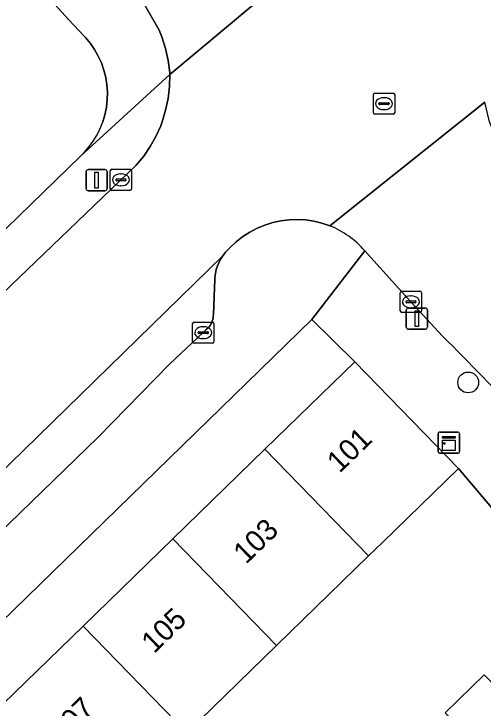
# Model space of a CAD drawing. Extents: x 159217 to 160349, y 381246 to 382172.
# Drawn here: x 159595.21 to 159617.29, y 381472.41 to 381505.08 of the extents above; entities that cross this region are included whole.
import ezdxf

# ---------------------------------------------------------------- set-up
doc = ezdxf.new("R2010")
doc.units = 0
for name, color, linetype in [('IMGEO_Boom', 7, 'Continuous'), ('IMGEO_Erf', 7, 'Continuous'), ('IMGEO_Haag', 7, 'Continuous'), ('IMGEO_Kast', 7, 'Continuous'), ('IMGEO_Kolk', 7, 'Continuous'), ('IMGEO_Lichtmast', 7, 'Continuous'), ('IMGEO_Muur', 7, 'Continuous'), ('IMGEO_Pand', 7, 'Continuous'), ('IMGEO_Pand_nummerreeks', 7, 'Continuous'), ('IMGEO_Parkeervlak_gesloten', 7, 'Continuous'), ('IMGEO_Rijbaan_lokaal_gesloten', 7, 'Continuous'), ('IMGEO_Rijbaan_lokaal_open', 7, 'Continuous'), ('IMGEO_Rioolput', 7, 'Continuous'), ('IMGEO_Voetpad_open', 7, 'Continuous')]:
    doc.layers.add(name, color=color, linetype=linetype)

msp = doc.modelspace()

# ---------------------------------------------------------------- linework, layer by layer
at = {"layer": 'IMGEO_Boom'}
msp.add_circle((159616.591, 381487.737), 0.489, dxfattribs=at)
at = {"layer": 'IMGEO_Erf'}
for points in [[(159599.397, 381500), (159599.498, 381500.339), (159599.569, 381500.686), (159599.609, 381501.038), (159599.616, 381501.392), (159599.593, 381501.746), (159599.537, 381502.095), (159599.451, 381502.439), (159599.334, 381502.773), (159599.188, 381503.096), (159599.014, 381503.404), (159598.813, 381503.695), (159598.586, 381503.968), (159598.538, 381504.02), (159597.784, 381504.824), (159590.258, 381513.08), (159579.357, 381524.607), (159568.355, 381536.063), (159563.311, 381541.305), (159563.005, 381541.713), (159558.611, 381546.23)], [(159539.065, 381507.732), (159532.866, 381501.64), (159533.78, 381500.754), (159533.92, 381500.619), (159533.288, 381500), (159529.255, 381496.05), (159533.836, 381491.161), (159535.126, 381489.785), (159537.084, 381488.236), (159540.616, 381491.711), (159541.068, 381492.156), (159539.687, 381493.589), (159546.206, 381500), (159559.807, 381513.376), (159572.893, 381500), (159586.111, 381486.49), (159598.343, 381498.393)], [(159594.136, 381472.057), (159598.471, 381476.273), (159602.688, 381480.373), (159607.022, 381484.589), (159611.256, 381488.706), (159609.226, 381490.692), (159573.857, 381456.231)], [(159623.522, 381474.971), (159616.137, 381483.686), (159612.553, 381480.201), (159611.904, 381479.569), (159607.569, 381475.354), (159603.352, 381471.254)], [(159615.499, 381472.19), (159617.339, 381473.98)]]:
    msp.add_lwpolyline(points, dxfattribs=at)
msp.add_arc((159595.668, 381501.297), 3.949, 312.6552, 340.8246, dxfattribs=at)
at = {"layer": 'IMGEO_Haag'}
for points in [[(159599.397, 381500), (159599.498, 381500.339), (159599.569, 381500.686), (159599.609, 381501.038), (159599.616, 381501.392), (159599.593, 381501.746), (159599.537, 381502.095), (159599.451, 381502.439), (159599.334, 381502.773), (159599.188, 381503.096), (159599.014, 381503.404), (159598.813, 381503.695), (159598.586, 381503.968), (159598.538, 381504.02), (159597.784, 381504.824), (159590.258, 381513.08), (159579.357, 381524.607), (159568.355, 381536.063), (159563.311, 381541.305), (159563.005, 381541.713), (159558.611, 381546.23)], [(159539.065, 381507.732), (159532.866, 381501.64), (159533.78, 381500.754), (159533.92, 381500.619), (159533.288, 381500), (159529.255, 381496.05), (159533.836, 381491.161), (159535.126, 381489.785), (159537.084, 381488.236), (159540.616, 381491.711), (159541.068, 381492.156), (159539.687, 381493.589), (159546.206, 381500), (159559.807, 381513.376), (159572.893, 381500), (159586.111, 381486.49), (159598.343, 381498.393)]]:
    msp.add_lwpolyline(points, dxfattribs=at)
msp.add_arc((159595.668, 381501.297), 3.949, 312.6552, 340.8246, dxfattribs=at)
at = {"layer": 'IMGEO_Kast'}
for p, q in [((159615.178, 381484.477), (159615.178, 381485.318)), ((159615.178, 381485.318), (159615.178, 381484.477)), ((159615.253, 381485.402), (159616.094, 381485.402)), ((159616.094, 381485.402), (159615.253, 381485.402)), ((159616.178, 381485.327), (159616.178, 381484.486)), ((159616.178, 381484.486), (159616.178, 381485.327)), ((159616.103, 381484.402), (159615.262, 381484.402)), ((159615.262, 381484.402), (159616.103, 381484.402))]:
    msp.add_line(p, q, dxfattribs=at)
for points in [[(159615.373, 381485.192), (159615.973, 381485.192), (159615.973, 381485.107), (159615.373, 381485.107), (159615.373, 381485.192)], [(159615.373, 381485.017), (159615.973, 381485.017), (159615.973, 381484.528), (159615.373, 381484.528), (159615.373, 381485.017)]]:
    msp.add_lwpolyline(points, dxfattribs=at)
msp.add_circle((159615.457, 381484.866), 0.0377, dxfattribs=at)
for centre, start, end in [((159615.256, 381485.324), 92.4484, 184.2845), ((159615.256, 381485.324), 92.4484, 184.2845), ((159616.1, 381485.324), 2.4484, 94.2845), ((159616.1, 381485.324), 2.4484, 94.2845), ((159615.256, 381484.48), 182.4484, 274.2845), ((159615.256, 381484.48), 182.4484, 274.2845), ((159616.1, 381484.48), 272.4484, 4.2845), ((159616.1, 381484.48), 272.4484, 4.2845)]:
    msp.add_arc(centre, 0.0779, start, end, dxfattribs=at)
at = {"layer": 'IMGEO_Kolk'}
for p, q in [((159599.75, 381496.846), (159599.75, 381497.698)), ((159599.825, 381497.772), (159600.677, 381497.772)), ((159600.751, 381497.698), (159600.751, 381496.846)), ((159600.052, 381497.315), (159600.45, 381497.315)), ((159600.238, 381497.552), (159600.263, 381497.552)), ((159600.009, 381497.266), (159600.009, 381497.278)), ((159600.447, 381497.229), (159600.049, 381497.229)), ((159600.261, 381496.992), (159600.236, 381496.992)), ((159600.493, 381497.278), (159600.493, 381497.266)), ((159600.677, 381496.772), (159599.825, 381496.772)), ((159613.394, 381491.105), (159613.394, 381491.957)), ((159613.469, 381492.031), (159614.321, 381492.031)), ((159613.882, 381491.811), (159613.907, 381491.811)), ((159614.395, 381491.957), (159614.395, 381491.105)), ((159613.653, 381491.525), (159613.653, 381491.537)), ((159614.091, 381491.488), (159613.693, 381491.488)), ((159613.696, 381491.574), (159614.094, 381491.574)), ((159614.137, 381491.537), (159614.137, 381491.525)), ((159613.905, 381491.251), (159613.88, 381491.251)), ((159614.321, 381491.031), (159613.469, 381491.031)), ((159603.623, 381489.653), (159603.623, 381490.505)), ((159603.698, 381490.579), (159604.55, 381490.579)), ((159604.624, 381490.505), (159604.624, 381489.653)), ((159603.925, 381490.122), (159604.323, 381490.122)), ((159604.111, 381490.359), (159604.136, 381490.359)), ((159603.882, 381490.073), (159603.882, 381490.085)), ((159604.32, 381490.036), (159603.922, 381490.036)), ((159604.134, 381489.799), (159604.109, 381489.799)), ((159604.366, 381490.085), (159604.366, 381490.073)), ((159604.55, 381489.579), (159603.698, 381489.579))]:
    msp.add_line(p, q, dxfattribs=at)
for points in [[(159599.75, 381496.846), (159599.75, 381497.698)], [(159599.825, 381497.772), (159600.677, 381497.772)], [(159600.751, 381497.698), (159600.751, 381496.846)], [(159600.677, 381496.772), (159599.825, 381496.772)], [(159613.394, 381491.105), (159613.394, 381491.957)], [(159613.469, 381492.031), (159614.321, 381492.031)], [(159614.395, 381491.957), (159614.395, 381491.105)], [(159614.321, 381491.031), (159613.469, 381491.031)], [(159603.623, 381489.653), (159603.623, 381490.505)], [(159603.698, 381490.579), (159604.55, 381490.579)], [(159604.624, 381490.505), (159604.624, 381489.653)], [(159604.55, 381489.579), (159603.698, 381489.579)]]:
    msp.add_lwpolyline(points, dxfattribs=at)
for centre, radius, start, end in [((159599.827, 381497.696), 0.0765, 91.552, 178.448), ((159599.827, 381497.696), 0.0765, 91.552, 178.448), ((159600.675, 381497.696), 0.0765, 1.552, 88.448), ((159600.675, 381497.696), 0.0765, 1.552, 88.448), ((159600.049, 381497.275), 0.0403, 85.8775, 175.7526), ((159600.454, 381497.277), 0.0386, 1.7309, 96.639), ((159600.046, 381497.265), 0.0366, 178.938, 274.7102), ((159600.45, 381497.272), 0.043, 264.8664, 352.4533), ((159599.827, 381496.848), 0.0765, 181.552, 268.448), ((159599.827, 381496.848), 0.0765, 181.552, 268.448), ((159600.675, 381496.848), 0.0765, 271.552, 358.448), ((159600.675, 381496.848), 0.0765, 271.552, 358.448), ((159613.471, 381491.955), 0.0765, 91.552, 178.448), ((159613.471, 381491.955), 0.0765, 91.552, 178.448), ((159614.319, 381491.955), 0.0765, 1.552, 88.448), ((159614.319, 381491.955), 0.0765, 1.552, 88.448), ((159613.693, 381491.534), 0.0403, 85.8775, 175.7526), ((159613.69, 381491.524), 0.0366, 178.938, 274.7102), ((159614.094, 381491.531), 0.043, 264.8664, 352.4533), ((159614.098, 381491.536), 0.0386, 1.7309, 96.639), ((159613.471, 381491.107), 0.0765, 181.552, 268.448), ((159613.471, 381491.107), 0.0765, 181.552, 268.448), ((159614.319, 381491.107), 0.0765, 271.552, 358.448), ((159614.319, 381491.107), 0.0765, 271.552, 358.448), ((159603.7, 381490.503), 0.0765, 91.552, 178.448), ((159603.7, 381490.503), 0.0765, 91.552, 178.448), ((159604.548, 381490.503), 0.0765, 1.552, 88.448), ((159604.548, 381490.503), 0.0765, 1.552, 88.448), ((159603.922, 381490.082), 0.0403, 85.8775, 175.7526), ((159604.327, 381490.084), 0.0386, 1.7309, 96.639), ((159603.919, 381490.072), 0.0366, 178.938, 274.7102), ((159604.323, 381490.079), 0.043, 264.8664, 352.4533), ((159603.7, 381489.655), 0.0765, 181.552, 268.448), ((159603.7, 381489.655), 0.0765, 181.552, 268.448), ((159604.548, 381489.655), 0.0765, 271.552, 358.448), ((159604.548, 381489.655), 0.0765, 271.552, 358.448)]:
    msp.add_arc(centre, radius, start, end, dxfattribs=at)
for centre, major_axis, ratio, start_param, end_param in [((159600.237, 381497.272), (-0.387, 0.002), 0.722429, 4.712389, 7.853982), ((159600.262, 381497.272), (-0.39, 0.002), 0.717154, 1.570796, 4.712389), ((159613.881, 381491.531), (-0.387, 0.002), 0.722429, 4.712389, 7.853982), ((159613.906, 381491.531), (-0.39, 0.002), 0.717154, 1.570796, 4.712389), ((159604.11, 381490.079), (-0.387, 0.002), 0.722429, 4.712389, 7.853982), ((159604.135, 381490.079), (-0.39, 0.002), 0.717154, 1.570796, 4.712389)]:
    msp.add_ellipse(centre, major_axis=major_axis, ratio=ratio, start_param=start_param, end_param=end_param, dxfattribs=at)
at = {"layer": 'IMGEO_Lichtmast'}
for p, q in [((159598.611, 381496.858), (159598.611, 381497.658)), ((159598.611, 381497.658), (159598.611, 381496.858)), ((159598.711, 381497.758), (159599.501, 381497.758)), ((159599.501, 381497.758), (159598.711, 381497.758)), ((159599.601, 381497.658), (159599.601, 381496.858)), ((159599.601, 381496.858), (159599.601, 381497.658)), ((159599.501, 381496.758), (159598.711, 381496.758)), ((159598.711, 381496.758), (159599.501, 381496.758)), ((159613.679, 381490.339), (159613.679, 381491.139)), ((159613.679, 381491.139), (159613.679, 381490.339)), ((159613.779, 381491.239), (159614.569, 381491.239)), ((159614.569, 381491.239), (159613.779, 381491.239)), ((159614.669, 381491.139), (159614.669, 381490.339)), ((159614.669, 381490.339), (159614.669, 381491.139)), ((159614.569, 381490.239), (159613.779, 381490.239)), ((159613.779, 381490.239), (159614.569, 381490.239))]:
    msp.add_line(p, q, dxfattribs=at)
for points in [[(159599.031, 381497.633), (159599.181, 381497.633), (159599.181, 381496.883), (159599.031, 381496.883), (159599.031, 381497.633)], [(159614.099, 381491.114), (159614.249, 381491.114), (159614.249, 381490.364), (159614.099, 381490.364), (159614.099, 381491.114)]]:
    msp.add_lwpolyline(points, dxfattribs=at)
for centre, start, end in [((159598.711, 381497.658), 90, 180), ((159598.711, 381497.658), 90, 180), ((159599.501, 381497.658), 0, 90), ((159599.501, 381497.658), 360, 90), ((159598.711, 381496.858), 180, 270), ((159598.711, 381496.858), 180, 270), ((159599.501, 381496.858), 270, 0), ((159599.501, 381496.858), 270, 0), ((159613.779, 381491.139), 90, 180), ((159613.779, 381491.139), 90, 180), ((159614.569, 381491.139), 0, 90), ((159614.569, 381491.139), 360, 90), ((159613.779, 381490.339), 180, 270), ((159613.779, 381490.339), 180, 270), ((159614.569, 381490.339), 270, 0), ((159614.569, 381490.339), 270, 0)]:
    msp.add_arc(centre, 0.1, start, end, dxfattribs=at)
at = {"layer": 'IMGEO_Muur'}
msp.add_lwpolyline([(159616.137, 381483.686), (159623.522, 381474.971)], dxfattribs=at)
at = {"layer": 'IMGEO_Pand'}
for points in [[(159611.904, 381479.569), (159612.553, 381480.201), (159616.137, 381483.686), (159611.256, 381488.706), (159607.022, 381484.589)], [(159611.904, 381479.569), (159607.022, 381484.589), (159602.688, 381480.373), (159607.569, 381475.354)], [(159602.688, 381480.373), (159598.471, 381476.273), (159603.352, 381471.254), (159607.569, 381475.354)], [(159599.017, 381467.038), (159603.352, 381471.254), (159598.471, 381476.273), (159594.136, 381472.057)], [(159617.339, 381473.98), (159615.499, 381472.19), (159618.009, 381469.609), (159619.849, 381471.399)]]:
    msp.add_lwpolyline(points, close=True, dxfattribs=at)
at = {"layer": 'IMGEO_Parkeervlak_gesloten'}
msp.add_lwpolyline([(159582.905, 381469.38), (159599.187, 381485.169), (159602.545, 381488.611), (159604.123, 381490.08), (159604.284, 381490.241), (159604.342, 381490.295), (159604.396, 381490.353), (159604.443, 381490.416), (159604.485, 381490.483), (159604.521, 381490.554), (159604.551, 381490.627), (159604.573, 381490.703), (159604.589, 381490.78), (159604.598, 381490.859), (159604.6, 381490.931), (159604.668, 381492.597), (159604.673, 381492.68), (159604.698, 381492.865), (159604.738, 381493.047), (159604.795, 381493.224), (159604.867, 381493.396), (159604.955, 381493.561), (159605.042, 381493.695), (159561.561, 381451.233)], dxfattribs=at)
at = {"layer": 'IMGEO_Rijbaan_lokaal_gesloten'}
for points in [[(159558.685, 381551.263), (159562.533, 381546.538), (159565.152, 381543.854), (159567.81, 381540.95), (159578.666, 381529.864), (159592.512, 381515.439), (159599.596, 381507.693), (159601.31, 381505.606), (159602.056, 381504.314), (159602.178, 381504.004), (159602.351, 381503.454), (159602.474, 381502.891), (159602.546, 381502.319), (159602.548, 381502.232), (159610.359, 381508.766), (159609.93, 381508.934), (159609.517, 381509.14), (159609.125, 381509.381), (159608.755, 381509.657), (159608.412, 381509.965)], [(159610.359, 381508.766), (159602.548, 381502.232), (159602.535, 381501.664), (159602.47, 381501.1), (159602.356, 381500.544), (159602.192, 381500), (159602.122, 381499.813), (159601.898, 381499.315), (159601.631, 381498.839), (159601.322, 381498.388), (159600.974, 381497.967), (159589.128, 381486.611), (159587.265, 381484.884)], [(159561.561, 381451.233), (159605.042, 381493.695), (159605.057, 381493.718), (159605.172, 381493.864), (159605.3, 381494), (159605.386, 381494.09), (159605.672, 381494.357), (159605.981, 381494.598), (159606.31, 381494.809), (159606.657, 381494.991), (159607.018, 381495.141), (159607.391, 381495.258), (159607.774, 381495.341), (159608.162, 381495.389), (159608.553, 381495.403), (159608.943, 381495.382), (159609.331, 381495.326), (159609.711, 381495.236), (159610.082, 381495.112), (159616.217, 381500), (159617.375, 381500.923)]]:
    msp.add_lwpolyline(points, dxfattribs=at)
at = {"layer": 'IMGEO_Rijbaan_lokaal_open'}
for points in [[(159641.019, 381472.846), (159632.882, 381482.53), (159627.569, 381488.79), (159622.028, 381494.6), (159619.537, 381497.357), (159618.573, 381498.425), (159618.392, 381498.626), (159618.148, 381498.941), (159617.933, 381499.277), (159617.75, 381499.631), (159617.598, 381500), (159617.375, 381500.923), (159616.217, 381500), (159610.082, 381495.112)], [(159611.723, 381493.938), (159613.896, 381491.532), (159615.382, 381489.917)]]:
    msp.add_lwpolyline(points, dxfattribs=at)
for centre, radius, start, end in [((159608.359, 381490.97), 4.486, 41.4231, 67.4157), ((159522.53, 381396.515), 131.702, 40.47009, 45.16941)]:
    msp.add_arc(centre, radius, start, end, dxfattribs=at)
at = {"layer": 'IMGEO_Rioolput'}
for p, q in [((159612.13, 381500.432), (159612.13, 381501.284)), ((159612.205, 381501.358), (159613.057, 381501.358)), ((159613.131, 381501.284), (159613.131, 381500.432)), ((159612.432, 381500.901), (159612.83, 381500.901)), ((159612.618, 381501.138), (159612.643, 381501.138)), ((159612.389, 381500.852), (159612.389, 381500.864)), ((159612.827, 381500.815), (159612.429, 381500.815)), ((159612.641, 381500.578), (159612.616, 381500.578)), ((159612.873, 381500.864), (159612.873, 381500.852)), ((159613.057, 381500.358), (159612.205, 381500.358))]:
    msp.add_line(p, q, dxfattribs=at)
for points in [[(159612.13, 381500.432), (159612.13, 381501.284)], [(159612.205, 381501.358), (159613.057, 381501.358)], [(159613.131, 381501.284), (159613.131, 381500.432)], [(159613.057, 381500.358), (159612.205, 381500.358)]]:
    msp.add_lwpolyline(points, dxfattribs=at)
for centre, radius, start, end in [((159612.207, 381501.282), 0.0765, 91.552, 178.448), ((159612.207, 381501.282), 0.0765, 91.552, 178.448), ((159613.055, 381501.282), 0.0765, 1.552, 88.448), ((159613.055, 381501.282), 0.0765, 1.552, 88.448), ((159612.429, 381500.861), 0.0403, 85.8775, 175.7526), ((159612.834, 381500.863), 0.0386, 1.7309, 96.639), ((159612.426, 381500.851), 0.0366, 178.938, 274.7102), ((159612.83, 381500.858), 0.043, 264.8664, 352.4533), ((159612.207, 381500.434), 0.0765, 181.552, 268.448), ((159612.207, 381500.434), 0.0765, 181.552, 268.448), ((159613.055, 381500.434), 0.0765, 271.552, 358.448), ((159613.055, 381500.434), 0.0765, 271.552, 358.448)]:
    msp.add_arc(centre, radius, start, end, dxfattribs=at)
for centre, major_axis, ratio, start_param, end_param in [((159612.617, 381500.858), (-0.387, 0.002), 0.722429, 4.712389, 7.853982), ((159612.642, 381500.858), (-0.39, 0.002), 0.717154, 1.570796, 4.712389)]:
    msp.add_ellipse(centre, major_axis=major_axis, ratio=ratio, start_param=start_param, end_param=end_param, dxfattribs=at)
at = {"layer": 'IMGEO_Voetpad_open'}
for points in [[(159558.611, 381546.23), (159563.005, 381541.713), (159563.311, 381541.305), (159568.355, 381536.063), (159579.357, 381524.607), (159590.258, 381513.08), (159597.784, 381504.824), (159598.538, 381504.02), (159598.586, 381503.968), (159598.813, 381503.695), (159599.014, 381503.404), (159599.188, 381503.096), (159599.334, 381502.773), (159599.451, 381502.439), (159599.537, 381502.095), (159599.593, 381501.746), (159599.616, 381501.392), (159599.609, 381501.038), (159599.569, 381500.686), (159599.498, 381500.339), (159599.397, 381500)], [(159598.343, 381498.393), (159602.548, 381502.232), (159602.546, 381502.319), (159602.474, 381502.891), (159602.351, 381503.454), (159602.178, 381504.004), (159602.056, 381504.314), (159601.31, 381505.606), (159599.596, 381507.693), (159592.512, 381515.439)], [(159600.974, 381497.967), (159601.322, 381498.388), (159601.631, 381498.839), (159601.898, 381499.315), (159602.122, 381499.813), (159602.192, 381500), (159602.356, 381500.544), (159602.47, 381501.1), (159602.535, 381501.664), (159602.548, 381502.232), (159598.343, 381498.393), (159586.111, 381486.49), (159584.818, 381485.232), (159571.706, 381472.473), (159568.157, 381468.986), (159562.025, 381462.991), (159559.843, 381460.857), (159544.065, 381445.432)], [(159587.265, 381484.884), (159589.128, 381486.611), (159600.974, 381497.967)], [(159610.082, 381495.112), (159609.711, 381495.236), (159609.331, 381495.326), (159608.943, 381495.382), (159608.553, 381495.403), (159608.162, 381495.389), (159607.774, 381495.341), (159607.391, 381495.258), (159607.018, 381495.141), (159606.657, 381494.991), (159606.31, 381494.809), (159605.981, 381494.598), (159605.672, 381494.357), (159605.386, 381494.09), (159605.3, 381494), (159605.172, 381493.864), (159605.057, 381493.718), (159605.042, 381493.695), (159604.955, 381493.561), (159604.867, 381493.396), (159604.795, 381493.224), (159604.738, 381493.047), (159604.698, 381492.865), (159604.673, 381492.68), (159604.668, 381492.597), (159604.6, 381490.931), (159604.598, 381490.859), (159604.589, 381490.78), (159604.573, 381490.703), (159604.551, 381490.627), (159604.521, 381490.554), (159604.485, 381490.483), (159604.443, 381490.416), (159604.396, 381490.353), (159604.342, 381490.295), (159604.284, 381490.241), (159604.123, 381490.08), (159602.545, 381488.611), (159599.187, 381485.169), (159582.905, 381469.38)], [(159539.277, 381422.576), (159544.261, 381427.431), (159554.351, 381437.259), (159558.85, 381441.633), (159563.183, 381445.848), (159567.473, 381450.018), (159571.816, 381454.242), (159572.669, 381455.073), (159573.857, 381456.231), (159609.226, 381490.692), (159611.723, 381493.938)], [(159615.382, 381489.917), (159613.896, 381491.532), (159611.723, 381493.938), (159609.226, 381490.692), (159611.256, 381488.706), (159616.137, 381483.686), (159623.522, 381474.971), (159623.653, 381474.817), (159624.932, 381473.307), (159625.029, 381473.192), (159651.623, 381441.001), (159654.605, 381437.657)]]:
    msp.add_lwpolyline(points, dxfattribs=at)
for centre, radius, start, end in [((159595.668, 381501.297), 3.949, 312.6552, 340.8246), ((159608.359, 381490.97), 4.486, 41.4231, 67.4157), ((159522.53, 381396.515), 131.702, 40.47009, 45.16941)]:
    msp.add_arc(centre, radius, start, end, dxfattribs=at)

# ---------------------------------------------------------------- texts
at = {"layer": 'IMGEO_Pand_nummerreeks'}
for s, p in [('101', (159610.538, 381483.434)), ('103', (159606.133, 381479.149)), ('105', (159601.808, 381474.944)), ('107', (159597.483, 381470.738))]:
    msp.add_text(s, height=1, rotation=44.2008, dxfattribs=at).set_placement(p)

doc.saveas('drawing.dxf')
